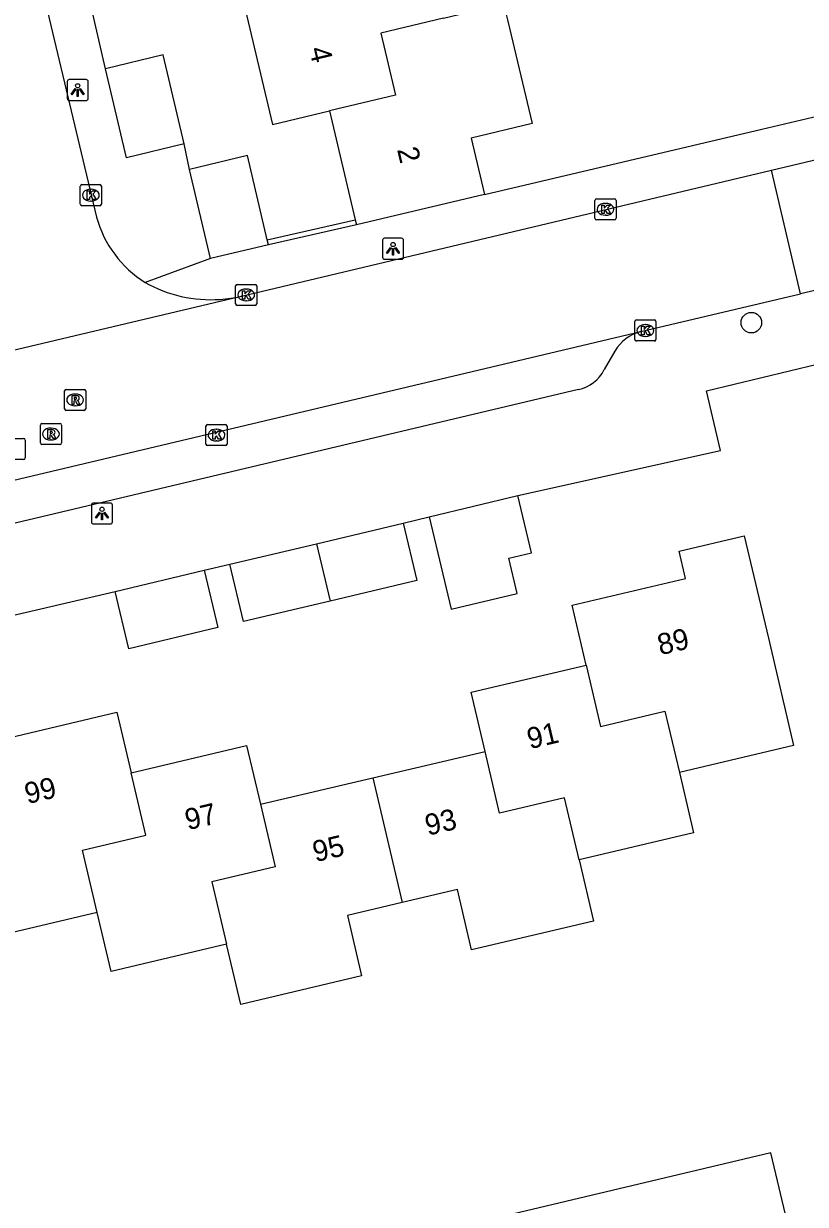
# Model space of a CAD drawing. Extents: x 158038 to 159242, y 380133 to 381214.
# Drawn here: x 158938.4 to 158975.6, y 380450.2 to 380506.3 of the extents above; entities that cross this region are included whole.
import ezdxf

# ---------------------------------------------------------------- set-up
doc = ezdxf.new("R2010")
doc.units = 0
for name, color, linetype in [('IMGEO_Boom', 7, 'Continuous'), ('IMGEO_Groenvoorziening', 7, 'Continuous'), ('IMGEO_Hek', 7, 'Continuous'), ('IMGEO_Kolk', 7, 'Continuous'), ('IMGEO_Lichtpunt', 7, 'Continuous'), ('IMGEO_Muur', 7, 'Continuous'), ('IMGEO_Pand', 7, 'Continuous'), ('IMGEO_Pand_nummerreeks', 7, 'Continuous'), ('IMGEO_Rijbaan_lokaal_open', 7, 'Continuous'), ('IMGEO_Rioolput', 7, 'Continuous'), ('IMGEO_Voetpad_open', 7, 'Continuous')]:
    doc.layers.add(name, color=color, linetype=linetype)

msp = doc.modelspace()

# ---------------------------------------------------------------- linework, layer by layer
at = {"layer": 'IMGEO_Boom'}
msp.add_circle((158973.026, 380492.057), 0.489, dxfattribs=at)
at = {"layer": 'IMGEO_Groenvoorziening'}
msp.add_lwpolyline([(159004.857, 380456.513), (159005.809, 380452.471), (159000.386, 380451.105), (158975.667, 380445.423), (158973.949, 380452.625), (158883.466, 380431.148)], dxfattribs=at)
at = {"layer": 'IMGEO_Hek'}
for points in [[(158973.521, 380501.247), (158980.518, 380502.896)], [(158960.344, 380498.141), (158973.521, 380501.247)]]:
    msp.add_lwpolyline(points, dxfattribs=at)
at = {"layer": 'IMGEO_Kolk'}
for p, q in [((158941.14, 380497.687), (158941.14, 380498.539)), ((158941.215, 380498.613), (158942.067, 380498.613)), ((158941.628, 380498.393), (158941.653, 380498.393)), ((158942.141, 380498.539), (158942.141, 380497.687)), ((158941.651, 380497.833), (158941.626, 380497.833)), ((158965.595, 380497.016), (158965.595, 380497.868)), ((158965.67, 380497.942), (158966.522, 380497.942)), ((158966.596, 380497.868), (158966.596, 380497.016)), ((158942.067, 380497.613), (158941.215, 380497.613)), ((158966.083, 380497.722), (158966.108, 380497.722)), ((158966.522, 380496.942), (158965.67, 380496.942)), ((158966.106, 380497.162), (158966.081, 380497.162)), ((158948.596, 380493.875), (158949.448, 380493.875)), ((158948.521, 380492.949), (158948.521, 380493.801)), ((158949.009, 380493.655), (158949.034, 380493.655)), ((158949.522, 380493.801), (158949.522, 380492.949)), ((158949.448, 380492.875), (158948.596, 380492.875)), ((158949.032, 380493.095), (158949.007, 380493.095)), ((158967.565, 380492.186), (158968.417, 380492.186)), ((158967.49, 380491.26), (158967.49, 380492.112)), ((158967.978, 380491.966), (158968.003, 380491.966)), ((158968.491, 380492.112), (158968.491, 380491.26)), ((158968.417, 380491.186), (158967.565, 380491.186)), ((158968.001, 380491.406), (158967.976, 380491.406)), ((158947.11, 380486.29), (158947.11, 380487.142)), ((158947.185, 380487.216), (158948.037, 380487.216)), ((158948.111, 380487.142), (158948.111, 380486.29)), ((158947.598, 380486.996), (158947.623, 380486.996)), ((158948.037, 380486.216), (158947.185, 380486.216)), ((158947.621, 380486.436), (158947.596, 380486.436))]:
    msp.add_line(p, q, dxfattribs=at)
for points in [[(158941.14, 380497.687), (158941.14, 380498.539)], [(158941.215, 380498.613), (158942.067, 380498.613)], [(158941.461, 380498.313), (158941.584, 380498.313), (158941.584, 380498.162), (158941.714, 380498.313), (158941.878, 380498.313), (158941.732, 380498.162), (158941.885, 380497.913), (158941.733, 380497.913), (158941.648, 380498.077), (158941.584, 380498.01), (158941.584, 380497.913), (158941.461, 380497.913), (158941.461, 380498.313)], [(158942.141, 380498.539), (158942.141, 380497.687)], [(158965.595, 380497.016), (158965.595, 380497.868)], [(158965.67, 380497.942), (158966.522, 380497.942)], [(158966.596, 380497.868), (158966.596, 380497.016)], [(158942.067, 380497.613), (158941.215, 380497.613)], [(158965.916, 380497.642), (158966.039, 380497.642), (158966.039, 380497.491), (158966.169, 380497.642), (158966.333, 380497.642), (158966.187, 380497.491), (158966.34, 380497.242), (158966.188, 380497.242), (158966.103, 380497.406), (158966.039, 380497.339), (158966.039, 380497.242), (158965.916, 380497.242), (158965.916, 380497.642)], [(158966.522, 380496.942), (158965.67, 380496.942)], [(158948.596, 380493.875), (158949.448, 380493.875)], [(158948.521, 380492.949), (158948.521, 380493.801)], [(158948.842, 380493.575), (158948.965, 380493.575), (158948.965, 380493.424), (158949.095, 380493.575), (158949.259, 380493.575), (158949.113, 380493.424), (158949.266, 380493.175), (158949.114, 380493.175), (158949.029, 380493.339), (158948.965, 380493.272), (158948.965, 380493.175), (158948.842, 380493.175), (158948.842, 380493.575)], [(158949.522, 380493.801), (158949.522, 380492.949)], [(158949.448, 380492.875), (158948.596, 380492.875)], [(158967.565, 380492.186), (158968.417, 380492.186)], [(158967.49, 380491.26), (158967.49, 380492.112)], [(158967.811, 380491.886), (158967.934, 380491.886), (158967.934, 380491.735), (158968.064, 380491.886), (158968.228, 380491.886), (158968.082, 380491.735), (158968.235, 380491.486), (158968.083, 380491.486), (158967.998, 380491.65), (158967.934, 380491.583), (158967.934, 380491.486), (158967.811, 380491.486), (158967.811, 380491.886)], [(158968.491, 380492.112), (158968.491, 380491.26)], [(158968.417, 380491.186), (158967.565, 380491.186)], [(158947.11, 380486.29), (158947.11, 380487.142)], [(158947.185, 380487.216), (158948.037, 380487.216)], [(158948.111, 380487.142), (158948.111, 380486.29)], [(158947.431, 380486.916), (158947.554, 380486.916), (158947.554, 380486.765), (158947.684, 380486.916), (158947.848, 380486.916), (158947.702, 380486.765), (158947.855, 380486.516), (158947.703, 380486.516), (158947.618, 380486.68), (158947.554, 380486.613), (158947.554, 380486.516), (158947.431, 380486.516), (158947.431, 380486.916)], [(158948.037, 380486.216), (158947.185, 380486.216)]]:
    msp.add_lwpolyline(points, dxfattribs=at)
for centre, start, end in [((158941.217, 380498.537), 91.552, 178.448), ((158941.217, 380498.537), 91.552, 178.448), ((158942.065, 380498.537), 1.552, 88.448), ((158942.065, 380498.537), 1.552, 88.448), ((158965.672, 380497.866), 91.552, 178.448), ((158965.672, 380497.866), 91.552, 178.448), ((158966.52, 380497.866), 1.552, 88.448), ((158966.52, 380497.866), 1.552, 88.448), ((158941.217, 380497.689), 181.552, 268.448), ((158941.217, 380497.689), 181.552, 268.448), ((158942.065, 380497.689), 271.552, 358.448), ((158942.065, 380497.689), 271.552, 358.448), ((158965.672, 380497.018), 181.552, 268.448), ((158965.672, 380497.018), 181.552, 268.448), ((158966.52, 380497.018), 271.552, 358.448), ((158966.52, 380497.018), 271.552, 358.448), ((158948.598, 380493.799), 91.552, 178.448), ((158948.598, 380493.799), 91.552, 178.448), ((158949.446, 380493.799), 1.552, 88.448), ((158949.446, 380493.799), 1.552, 88.448), ((158948.598, 380492.951), 181.552, 268.448), ((158948.598, 380492.951), 181.552, 268.448), ((158949.446, 380492.951), 271.552, 358.448), ((158949.446, 380492.951), 271.552, 358.448), ((158967.567, 380492.11), 91.552, 178.448), ((158967.567, 380492.11), 91.552, 178.448), ((158968.415, 380492.11), 1.552, 88.448), ((158968.415, 380492.11), 1.552, 88.448), ((158967.567, 380491.262), 181.552, 268.448), ((158967.567, 380491.262), 181.552, 268.448), ((158968.415, 380491.262), 271.552, 358.448), ((158968.415, 380491.262), 271.552, 358.448), ((158947.187, 380487.14), 91.552, 178.448), ((158947.187, 380487.14), 91.552, 178.448), ((158948.035, 380487.14), 1.552, 88.448), ((158948.035, 380487.14), 1.552, 88.448), ((158947.187, 380486.292), 181.552, 268.448), ((158947.187, 380486.292), 181.552, 268.448), ((158948.035, 380486.292), 271.552, 358.448), ((158948.035, 380486.292), 271.552, 358.448)]:
    msp.add_arc(centre, 0.0765, start, end, dxfattribs=at)
for centre, major_axis, ratio, start_param, end_param in [((158941.627, 380498.113), (-0.387, 0.002), 0.722429, 4.712389, 7.853982), ((158941.652, 380498.113), (-0.39, 0.002), 0.717154, 1.570796, 4.712389), ((158966.082, 380497.442), (-0.387, 0.002), 0.722429, 4.712389, 7.853982), ((158966.107, 380497.442), (-0.39, 0.002), 0.717154, 1.570796, 4.712389), ((158949.008, 380493.375), (-0.387, 0.002), 0.722429, 4.712389, 7.853982), ((158949.033, 380493.375), (-0.39, 0.002), 0.717154, 1.570796, 4.712389), ((158967.977, 380491.686), (-0.387, 0.002), 0.722429, 4.712389, 7.853982), ((158968.002, 380491.686), (-0.39, 0.002), 0.717154, 1.570796, 4.712389), ((158947.597, 380486.716), (-0.387, 0.002), 0.722429, 4.712389, 7.853982), ((158947.622, 380486.716), (-0.39, 0.002), 0.717154, 1.570796, 4.712389)]:
    msp.add_ellipse(centre, major_axis=major_axis, ratio=ratio, start_param=start_param, end_param=end_param, dxfattribs=at)
at = {"layer": 'IMGEO_Lichtpunt'}
for p, q in [((158940.516, 380503.511), (158940.516, 380502.704)), ((158940.516, 380503.511), (158940.516, 380502.704)), ((158941.418, 380503.606), (158940.61, 380503.606)), ((158941.418, 380503.606), (158940.61, 380503.606)), ((158941.512, 380502.704), (158941.512, 380503.511)), ((158941.512, 380502.704), (158941.512, 380503.511)), ((158940.61, 380502.61), (158941.418, 380502.61)), ((158940.61, 380502.61), (158941.418, 380502.61)), ((158956.405, 380496.064), (158955.597, 380496.064)), ((158956.405, 380496.064), (158955.597, 380496.064)), ((158955.503, 380495.969), (158955.503, 380495.162)), ((158955.503, 380495.969), (158955.503, 380495.162)), ((158956.499, 380495.162), (158956.499, 380495.969)), ((158956.499, 380495.162), (158956.499, 380495.969)), ((158955.597, 380495.068), (158956.405, 380495.068)), ((158955.597, 380495.068), (158956.405, 380495.068)), ((158941.67, 380483.394), (158941.67, 380482.587)), ((158941.67, 380483.394), (158941.67, 380482.587)), ((158942.572, 380483.489), (158941.764, 380483.489)), ((158942.572, 380483.489), (158941.764, 380483.489)), ((158942.666, 380482.587), (158942.666, 380483.394)), ((158942.666, 380482.587), (158942.666, 380483.394)), ((158941.764, 380482.493), (158942.572, 380482.493)), ((158941.764, 380482.493), (158942.572, 380482.493))]:
    msp.add_line(p, q, dxfattribs=at)
for points in [[(158940.89, 380503.175), (158940.929, 380503.147), (158940.741, 380502.885), (158940.703, 380502.912), (158940.89, 380503.175)], [(158940.992, 380503.127), (158941.039, 380503.127), (158941.039, 380502.805), (158940.992, 380502.805), (158940.992, 380503.127)], [(158941.102, 380503.147), (158941.14, 380503.174), (158941.327, 380502.912), (158941.288, 380502.884), (158941.102, 380503.147)], [(158955.877, 380495.633), (158955.916, 380495.605), (158955.728, 380495.343), (158955.69, 380495.37), (158955.877, 380495.633)], [(158955.979, 380495.585), (158956.026, 380495.585), (158956.026, 380495.263), (158955.979, 380495.263), (158955.979, 380495.585)], [(158956.089, 380495.605), (158956.127, 380495.632), (158956.314, 380495.37), (158956.275, 380495.342), (158956.089, 380495.605)], [(158942.044, 380483.058), (158942.083, 380483.03), (158941.895, 380482.768), (158941.857, 380482.795), (158942.044, 380483.058)], [(158942.146, 380483.01), (158942.193, 380483.01), (158942.193, 380482.688), (158942.146, 380482.688), (158942.146, 380483.01)], [(158942.256, 380483.03), (158942.294, 380483.057), (158942.481, 380482.795), (158942.442, 380482.767), (158942.256, 380483.03)]]:
    msp.add_lwpolyline(points, dxfattribs=at)
for centre in [(158941.015, 380503.309), (158956.002, 380495.767), (158942.169, 380483.192)]:
    msp.add_circle(centre, 0.0994, dxfattribs=at)
for centre, start, end in [((158940.61, 380503.511), 90, 180), ((158940.61, 380503.511), 90, 180), ((158941.418, 380503.511), 0, 90), ((158941.418, 380503.511), 0, 90), ((158940.61, 380502.704), 180, 270), ((158940.61, 380502.704), 180, 270), ((158941.418, 380502.704), 270, 0), ((158941.418, 380502.704), 270, 360), ((158955.597, 380495.969), 90, 180), ((158955.597, 380495.969), 90, 180), ((158956.405, 380495.969), 0, 90), ((158956.405, 380495.969), 0, 90), ((158955.597, 380495.162), 180, 270), ((158955.597, 380495.162), 180, 270), ((158956.405, 380495.162), 270, 0), ((158956.405, 380495.162), 270, 360), ((158941.764, 380483.394), 90, 180), ((158941.764, 380483.394), 90, 180), ((158942.572, 380483.394), 0, 90), ((158942.572, 380483.394), 0, 90), ((158941.764, 380482.587), 180, 270), ((158941.764, 380482.587), 180, 270), ((158942.572, 380482.587), 270, 0), ((158942.572, 380482.587), 270, 360)]:
    msp.add_arc(centre, 0.0946, start, end, dxfattribs=at)
at = {"layer": 'IMGEO_Muur'}
for points in [[(158950.021, 380495.995), (158954.204, 380496.937)], [(158954.257, 380496.703), (158950.076, 380495.761)]]:
    msp.add_lwpolyline(points, dxfattribs=at)
at = {"layer": 'IMGEO_Pand'}
for points in [[(158948.969, 380506.945), (158950.271, 380501.469), (158952.981, 380502.114)], [(158958.39, 380506.523), (158961.256, 380507.204), (158961.451, 380506.382), (158962.608, 380501.517), (158959.709, 380500.828), (158960.344, 380498.141)], [(158958.39, 380506.523), (158955.419, 380505.817), (158956.122, 380502.861), (158952.981, 380502.114)], [(158946.079, 380500.545), (158945.081, 380504.786), (158942.333, 380504.122)], [(158946.079, 380500.545), (158943.331, 380499.882), (158942.333, 380504.122)], [(158952.981, 380502.114), (158954.204, 380496.937)], [(158950.021, 380495.995), (158949.085, 380499.996), (158946.333, 380499.334)], [(158947.325, 380495.099), (158946.333, 380499.334)], [(158960.344, 380498.141), (158954.257, 380496.703)], [(158954.204, 380496.937), (158954.257, 380496.703)], [(158950.076, 380495.761), (158947.325, 380495.099)], [(158950.076, 380495.761), (158950.021, 380495.995)], [(158957.71, 380482.836), (158961.931, 380483.847)], [(158957.71, 380482.836), (158958.363, 380480.113), (158958.764, 380478.441), (158961.896, 380479.192), (158961.495, 380480.863), (158962.583, 380481.124), (158961.931, 380483.847)], [(158952.365, 380481.555), (158956.484, 380482.533)], [(158956.484, 380482.533), (158957.131, 380479.809), (158953.011, 380478.831)], [(158948.245, 380480.576), (158952.365, 380481.555)], [(158952.365, 380481.555), (158953.011, 380478.831)], [(158965.174, 380475.787), (158964.504, 380478.633), (158969.894, 380479.904), (158969.589, 380481.2), (158972.69, 380481.931), (158973.837, 380477.065), (158975.037, 380471.97), (158969.607, 380470.69)], [(158953.011, 380478.831), (158948.891, 380477.852), (158948.245, 380480.576)], [(158942.801, 380479.288), (158947.022, 380480.294)], [(158947.022, 380480.294), (158947.671, 380477.571), (158943.45, 380476.564), (158942.801, 380479.288)], [(158960.373, 380471.69), (158959.711, 380474.5), (158965.174, 380475.787)], [(158965.174, 380475.787), (158965.859, 380472.878), (158968.921, 380473.599), (158969.607, 380470.69)], [(158934.255, 380472.822), (158937.188, 380473.513), (158937.48, 380472.273), (158942.879, 380473.545), (158943.555, 380470.675)], [(158943.555, 380470.675), (158949.038, 380471.967), (158949.696, 380469.174)], [(158955.035, 380470.432), (158960.373, 380471.69)], [(158964.839, 380466.544), (158964.147, 380469.48), (158961.065, 380468.754), (158960.373, 380471.69)], [(158941.944, 380464.034), (158941.245, 380467), (158944.254, 380467.709), (158943.555, 380470.675)], [(158949.696, 380469.174), (158955.035, 380470.432)], [(158955.035, 380470.432), (158956.435, 380464.507)], [(158969.607, 380470.69), (158970.282, 380467.827), (158964.839, 380466.544)], [(158949.696, 380469.174), (158950.396, 380466.203), (158947.387, 380465.495), (158948.087, 380462.524)], [(158964.839, 380466.544), (158965.526, 380463.628), (158959.733, 380462.263), (158959.059, 380465.125), (158956.435, 380464.507)], [(158956.435, 380464.507), (158953.829, 380463.893), (158954.506, 380461.021), (158948.76, 380459.667), (158948.087, 380462.524)], [(158941.944, 380464.034), (158936.628, 380462.781)], [(158948.087, 380462.524), (158942.604, 380461.232), (158941.944, 380464.034)]]:
    msp.add_lwpolyline(points, dxfattribs=at)
at = {"layer": 'IMGEO_Rijbaan_lokaal_open'}
for points in [[(158934.264, 380529.122), (158941.908, 380497.067)], [(158973.979, 380499.304), (158978.724, 380500.43)], [(158948.8, 380493.312), (158973.979, 380499.304)], [(158975.364, 380493.421), (158973.979, 380499.304)], [(158980.111, 380494.53), (158975.364, 380493.421)], [(158948.8, 380493.312), (158948.712, 380493.285), (158932.127, 380489.349)], [(158967.769, 380491.632), (158975.364, 380493.421)], [(158922.543, 380480.912), (158967.769, 380491.632)]]:
    msp.add_lwpolyline(points, dxfattribs=at)
for centre, radius, start, end in [((158947.091, 380498.521), 5.384, 195.6735, 237.7162), ((158947.357, 380499.553), 6.406, 240.638, 273.7771), ((158947.354, 380499.562), 6.415, 273.7984, 283.0271)]:
    msp.add_arc(centre, radius, start, end, dxfattribs=at)
at = {"layer": 'IMGEO_Rioolput'}
for p, q in [((158940.393, 380487.961), (158940.393, 380488.813)), ((158940.468, 380488.887), (158941.32, 380488.887)), ((158941.394, 380488.813), (158941.394, 380487.961)), ((158940.881, 380488.667), (158940.906, 380488.667)), ((158941.32, 380487.887), (158940.468, 380487.887)), ((158940.904, 380488.107), (158940.879, 380488.107)), ((158939.243, 380486.341), (158939.243, 380487.193)), ((158939.318, 380487.267), (158940.17, 380487.267)), ((158940.244, 380487.193), (158940.244, 380486.341)), ((158937.593, 380486.556), (158938.445, 380486.556)), ((158939.731, 380487.047), (158939.756, 380487.047)), ((158938.519, 380486.482), (158938.519, 380485.63)), ((158940.17, 380486.267), (158939.318, 380486.267)), ((158939.754, 380486.487), (158939.729, 380486.487)), ((158938.445, 380485.556), (158937.593, 380485.556))]:
    msp.add_line(p, q, dxfattribs=at)
for points in [[(158940.393, 380487.961), (158940.393, 380488.813)], [(158940.468, 380488.887), (158941.32, 380488.887)], [(158941.394, 380488.813), (158941.394, 380487.961)], [(158940.982, 380488.585), (158940.73, 380488.587), (158940.73, 380488.187)], [(158940.73, 380488.187), (158940.854, 380488.187), (158940.854, 380488.349), (158940.865, 380488.349)], [(158940.908, 380488.506), (158940.854, 380488.506), (158940.854, 380488.425)], [(158940.854, 380488.425), (158940.906, 380488.425)], [(158940.912, 380488.32), (158940.983, 380488.187), (158941.123, 380488.187), (158941.058, 380488.313)], [(158941.32, 380487.887), (158940.468, 380487.887)], [(158939.243, 380486.341), (158939.243, 380487.193)], [(158939.318, 380487.267), (158940.17, 380487.267)], [(158940.244, 380487.193), (158940.244, 380486.341)], [(158937.593, 380486.556), (158938.445, 380486.556)], [(158939.832, 380486.965), (158939.58, 380486.967), (158939.58, 380486.567)], [(158939.58, 380486.567), (158939.704, 380486.567), (158939.704, 380486.729), (158939.715, 380486.729)], [(158939.758, 380486.886), (158939.704, 380486.886), (158939.704, 380486.805)], [(158939.704, 380486.805), (158939.756, 380486.805)], [(158939.762, 380486.7), (158939.833, 380486.567), (158939.973, 380486.567), (158939.908, 380486.693)], [(158938.519, 380486.482), (158938.519, 380485.63)], [(158940.17, 380486.267), (158939.318, 380486.267)], [(158938.445, 380485.556), (158937.593, 380485.556)]]:
    msp.add_lwpolyline(points, dxfattribs=at)
for centre, radius, start, end in [((158940.47, 380488.811), 0.0765, 91.552, 178.448), ((158940.47, 380488.811), 0.0765, 91.552, 178.448), ((158941.318, 380488.811), 0.0765, 1.552, 88.448), ((158941.318, 380488.811), 0.0765, 1.552, 88.448), ((158940.864, 380488.296), 0.0533, 26.0293, 88.6989), ((158940.89, 380488.614), 0.19, 274.7715, 282.9687), ((158940.914, 380488.41), 0.0964, 77.0061, 93.1865), ((158940.928, 380488.467), 0.0378, 276.6634, 79.6772), ((158940.981, 380488.475), 0.109, 350.3612, 89.416), ((158940.979, 380488.475), 0.112, 277.5842, 350.9817), ((158940.963, 380488.26), 0.108, 29.5134, 73.7905), ((158940.47, 380487.963), 0.0765, 181.552, 268.448), ((158940.47, 380487.963), 0.0765, 181.552, 268.448), ((158941.318, 380487.963), 0.0765, 271.552, 358.448), ((158941.318, 380487.963), 0.0765, 271.552, 358.448), ((158939.32, 380487.191), 0.0765, 91.552, 178.448), ((158939.32, 380487.191), 0.0765, 91.552, 178.448), ((158940.168, 380487.191), 0.0765, 1.552, 88.448), ((158940.168, 380487.191), 0.0765, 1.552, 88.448), ((158938.443, 380486.48), 0.0765, 1.552, 88.448), ((158938.443, 380486.48), 0.0765, 1.552, 88.448), ((158939.714, 380486.676), 0.0533, 26.0293, 88.6989), ((158939.74, 380486.994), 0.19, 274.7715, 282.9687), ((158939.764, 380486.79), 0.0964, 77.0061, 93.1865), ((158939.778, 380486.847), 0.0378, 276.6634, 79.6772), ((158939.831, 380486.855), 0.109, 350.3612, 89.416), ((158939.829, 380486.855), 0.112, 277.5842, 350.9817), ((158939.813, 380486.64), 0.108, 29.5134, 73.7905), ((158939.32, 380486.343), 0.0765, 181.552, 268.448), ((158939.32, 380486.343), 0.0765, 181.552, 268.448), ((158940.168, 380486.343), 0.0765, 271.552, 358.448), ((158940.168, 380486.343), 0.0765, 271.552, 358.448), ((158938.443, 380485.632), 0.0765, 271.552, 358.448), ((158938.443, 380485.632), 0.0765, 271.552, 358.448)]:
    msp.add_arc(centre, radius, start, end, dxfattribs=at)
for centre, major_axis, ratio, start_param, end_param in [((158940.88, 380488.387), (-0.387, 0.002), 0.722429, 4.712389, 7.853982), ((158940.905, 380488.387), (-0.39, 0.002), 0.717154, 1.570796, 4.712389), ((158939.73, 380486.767), (-0.387, 0.002), 0.722429, 4.712389, 7.853982), ((158939.755, 380486.767), (-0.39, 0.002), 0.717154, 1.570796, 4.712389)]:
    msp.add_ellipse(centre, major_axis=major_axis, ratio=ratio, start_param=start_param, end_param=end_param, dxfattribs=at)
at = {"layer": 'IMGEO_Voetpad_open'}
for points in [[(158942.333, 380504.122), (158941.127, 380509.357)], [(158960.344, 380498.141), (158973.521, 380501.247), (158980.518, 380502.896)], [(158946.333, 380499.334), (158946.079, 380500.545)], [(158947.325, 380495.099), (158944.216, 380493.97)], [(158961.931, 380483.847), (158971.556, 380485.976), (158970.89, 380488.824), (158976.151, 380490.08), (158977.96, 380490.512), (158981.696, 380491.447)], [(158966.54, 380490.701), (158966.032, 380489.825)], [(158964.814, 380488.882), (158898.242, 380473.095)], [(158956.484, 380482.533), (158957.71, 380482.836)], [(158947.022, 380480.294), (158948.245, 380480.576)], [(158937.632, 380478.075), (158942.801, 380479.288)]]:
    msp.add_lwpolyline(points, dxfattribs=at)
for centre, radius, start, end in [((158968.234, 380489.741), 1.947, 103.8223, 150.4675), ((158964.473, 380490.58), 1.732, 281.3502, 334.1453)]:
    msp.add_arc(centre, radius, start, end, dxfattribs=at)

# ---------------------------------------------------------------- texts
at = {"layer": 'IMGEO_Pand_nummerreeks'}
for s, rotation, p in [('4', 283.3746, (158952.007, 380505.058)), ('2', 283.3555, (158956.187, 380500.286)), ('89', 13.2684, (158968.697, 380476.253)), ('91', 13.2563, (158962.499, 380471.788)), ('99', 13.1602, (158938.624, 380469.182)), ('97', 13.2592, (158946.244, 380467.939)), ('93', 13.2597, (158957.651, 380467.679)), ('95', 13.2597, (158952.312, 380466.421))]:
    msp.add_text(s, height=1, rotation=rotation, dxfattribs=at).set_placement(p)

doc.saveas('drawing.dxf')
